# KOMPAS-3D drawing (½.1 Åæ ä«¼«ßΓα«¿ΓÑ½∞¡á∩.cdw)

Views: Вид 1
Referenced files in C:\Program Files\ASCON\KOMPAS-3D V10\Sys\: Graphic.lcs
Referenced files in \\F-server\проектирование\Проекты\РЗА и ПА Тюменские РС\4. Проект\ЭП\Домостроительная\Рабочая документация\: План ПС Домостроительная.cdw
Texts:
  Ирина
  Текст на чертеже
  Размерные надписи
  Шероховатость
  Линия-выноска #1
  Линия-выноска #2
  Линия-выноска #3
  Отклонения формы и база
  Заголовок таблицы
  Ячейка таблицы
  Стрелка вида
  Обозначение изменения
  Фигурная скобка
  Номер узла
  Марка координационной оси
  VRCB
  Выносная надпись
  Обозначение узла
  Марка/позиционное обозначение с линией-выноской
  Марка/позиционное обозначение на линии
  Марка/позиционное обозначение без линии-выноски
  Normal
  Лит-Масса-Масштаб
  Материал-Предприятие
  Title Specification
  Body Specification ( left align )
  Body Specificaton ( centered )
  Без имени
  heading 1
  Знак Знак Знак Знак Знак Знак
  Verdana
  Body Text
  MS Sans Serif
  Txt
  Simplex
  TXT
  Обычный
  Термин
  Список определений
  Адрес
  Цитаты
  Форматированный
  Courier New
  Z-конец формы
  Z-начало формы
  Additional DXF text style 0
  Абзац Знак
  Body Text 3
  Title
  ТекстШаг1
  Шрифт 2.5
  Заголовки
  txt
  heading 2
  AGOpus
  footer
  Денис
  RUSTXT
  Обычный (веб)
  ООббыыччнныыйй
  Definition Term
  Definition List
  Address
  Blockquote
  Preformatted
  z-Bottom of Form
  z-Top of Form
  header
  NormalParagraphStyle
  ссылки
  Подпись в квадратике
  табл
  цепи
  Маркировка
  клеммы, контакты
  тексты табл
  Тексты. 3,2
  ЗОНА_привяз
  текст переноса
  ТТееррммиинн
  ССппииссоокк ооппррееддееллеенниийй
  ААддрреесс
  ЦЦииттааттыы
  ФФооррммааттиирроовваанннныыйй
  Z-ккооннеецц ффооррммыы
  Z-ннааччааллоо ффооррммыы
  GOST 2.304 type A
  rustxt
  heading 8
  heading 3
  heading 6
  heading 7
  russ
  heading 4
  heading 5
  heading 9
  HeliosLight
  Pa3
  Pa1
  Три с половиной
  style2
  Table Contents
  Table Heading
  ГОСТ_МНЕ
  ESK - Обозначение
  маркировка
  ISOCP
  ROMANS
  SIMPLEX
  Текст 3,5
  Tahoma
  CNBNDG+TimesNewRoman
  Subtitle
  FR5
  ISOCPEUR
  romanc
  Аппараты
  Ссылки
  подписи
  Состав чартежа
  Клеммник текст
  ячейка табл.
  Пояснения
  CC С?т?и?л?ь? П?о? ц?е?н?т?р?у?
  Normal (Web)
  Размеры
  Ошиновка
  позиции
  Демонтаж
  Монтаж
  Поз.
  Перечень элементов
  Кол.
  ед., кг
  Приме-
  чание
  ГОСТ 12965-74*
  ГОСТ 689-69*
  ТУ16-517.646-80
  ТУ16-517.124-78
  ТУ16-520.228-80
  ГОСТ 9984-79*
  ТУ16-521.264-79
  ТУ16-521.089-75
  ГОСТ 20479-79*
  ГОСТ 12022-76*
  ГОСТ 839-80
  ТУ16-521.297-81
  ГОСТ 15581-80
  РМ2 140002 ТУ
  ГОСТ 15150-69
  Трансформатор силовой
  ТРДН-25000/110-66
  Разъединитель трёхполюсный с 2
  комплектами заземляющих ножей
  РНДЗ-2-110/1000У1 с приводом У1
  Разъединитель трёхполюсный с 1
  комплектом заземляющих ножей
  РНДЗ-1-110/1000У1 с приводом У1
  Трансформатор тока ТФЗМ-110Б-1У1
  Трансформатор напряжения
  НКФ-110-57 У1
  Выключатель масляный ВМТ-110Б-
  -20/1000 У1 с ППК-2300 У1
  Изолятор опорный на 110 кВ
  ИОС-110-100 У1
  Разрядник вентильный РВС-110 кВ
  Заземлитель однополюсный ЗОН-
  -110м-II У1 с приводом ПРН-11 У1
  Разрядник вентильный 35 кВ РВС-35
  Изолятор опорный 10 кВ ОНШ-10-500
  Изолятор проходной 10 кВ
  ИП-10/1600-1250 У1
  Трансформатор собственных нужд
  Провод сталеалюминиевый АС-240/32
  Провод сталеалюминиевый АС-400/51
  Заградитель высокочастотный
  ВЗ-630-0,5
  Конденсатор связи
  СМПВ-110/ 3 -6,4
  Фильтр присоединения ФПУ-6400
  Разъединитель однополюсный
  РВО-10/400
  Провод сталеалюминиевый
  АС-240/32
  ВЗ-630-0,5-У1
  СМПВ-110/ 3 -6,4 У1
  Фильтр присоединения
  ФП-6400пФ У1
  проект.
  ВЛ 110 кВ
  Тюмень-500
  Тюменская ТЭЦ
  - предупреждающий знак
  "Опасно. Возможно падение груза"
  "Опасность поражения электрическим током"
  - стоянка крана во время производства работ
  Экспликация зданий и сооружений
  Номер
  на плане
  Постоянные здания и сооружения
  ОПУ-IV
  Существующее
  ЗРУ-10 кВ
  Трансформатор 1Т, маслоприемник
  Существующий
  Трансформатор 2Т, маслоприемник
  Временные здания и сооружения
  III
  Вагон-дом для кратковременного отдых рабочих
  Уборная
  Дизельная электростанция
  Контейнеры для ТБО (0,75м 3 ) и жидких хоз.-быт.стоков(1м 3 )
  «Екатерина» 9,0х3,0
  Туалетная кабина "Люкс"
  ОАО ПКТИпромстрой
  - стенд с противопожарным инвентарем
  - знак ограничения поворота стрелы
  - опасная зона работы
  при перемещении грузов
  Примечания:
  1. Для нужд строительства (размещение задействованного в строительстве персонала, обеспечение электроэнергией) использовать
  временные мобильные инвентарные здания;
  2. При выполнении всех строительно-монтажных работ на площадке необходимо руководствоваться требованиями СНиП 12-03-2001
  "Безопасность труда в строительстве. Общие требования",  СНиП 12-04-2002 "Безопасность труда в строительстве. Строительное
  производство", а также ПОТ-РМ-016-2001/РД 153-34.0-03.150-00 "Межотраслевые правила по охране труда  (правила безопасности)
  при эксплуатации электроустановок";
  3. На паспорте-стенде строительного объекта  должен быть план пожарной защиты с нанесенными строящимися и вспомогательными
  зданиями и сооружениями, въездами, подъездами, местонахождениями водоисточников, средств пожаротушения и связи (согласно
  ППБ-01-03 п.575);
  4. Наружное освещение строительной площадки осуществляется за счет существующего освещения;
  5. Под временные сооружения (поз. II, III и IV) устраивается площадка из дорожных плит ПД 60-20 на щебеночном основании толщиной 15см;
  6. На период строительства для электроснабжения временных зданий и сооружений использовать дизельную  электростанцию.
  Прокладку кабеля от дизельной электростанции до вагончиков выполнить в воздушном исполнении в гофрированной трубе диаметром
  30 мм, на вагончиках кабель закрепить скобами. Щиток временного электроснабжения навесить на стенку вагона-дома для отдыха рабочих;
  7. Тонкой линией изображено существующее оборудование, замена которого проектом не предусматривается,  утолщенной - демонтируемое
  оборудование.
  - пути перемещения
  строительной техники
  Условные обозначения:
  - паспорт-стенд строительного
  объекта
  - запрещающий знак ограничения
  скорости движения автомобиля
  АГП-22
  КМУ ИНМАН ИМ-150
  Бортовой автомобиль КамАЗ 43114-027-02
  АТ ППР#010#0104
  АГП
  Автогидроподъемник АГП-18-04
  АГП ППР#140#0102
  Шашерин
  Королева
  Разраб.
  Перезавод ВЛ на ПС Тюмень. Реконструкция устройств
  РЗ и ПА на обратных концах отходящих ВЛ,
  ВОЛС Тюменского ТПО
  Строительный генеральный план
  Ведомость эскизного проекта
  ПС 110/10 кВ Домостроительная
  ГИП
  Матвеев
  Ромин
Dimensions and other numbers on the sheet: 16/01-ПОД; 7; 2,5; 1,8; 2.5; 3,2_; 3.5; 3,2; 2,5 (контакты, клеммы); 3,2 (надписи); 3,2 (Зоны); 5; 2,5_01; 2,5_3; 3,5_01; 3,5_tabl; 5_заголовок; 2,3_; 3,2_зона не привяз; 3,5; 3.2 маркировка; 3,2 элементы; 3,2 линия; 3,2 таблица; 2,5 грязносинь; 2.5 курсив; 2.5_Э5_надписи; 2.5_Э5_ссылки; 2.5_кабель; 3.2; 2.5 надписи; 3 и 5; 5,0_белый_подчёркнутый; 3.2 фиол; 3.2 (текст); 8000; 4350; 6000; 3000; 2500; 2000; 1400; 7500; 1500; 2600; 10000; 1900; 5500; 3500; 9000; 3900; 3600; 60000; 11000; 12000; 920; 4000; 3380; 1200; 2; 4; 6; 3; 1; 9; 10; 8; 17; 18; 19; 16; 13; 15; 12; 11; 14; 4500; 1000; 20; 21; 22; 23; 24; 10/0,4 кВ ТМ-100/10-66; 60; 0,921; 168; 210; 6,3; 9,6; 05.13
